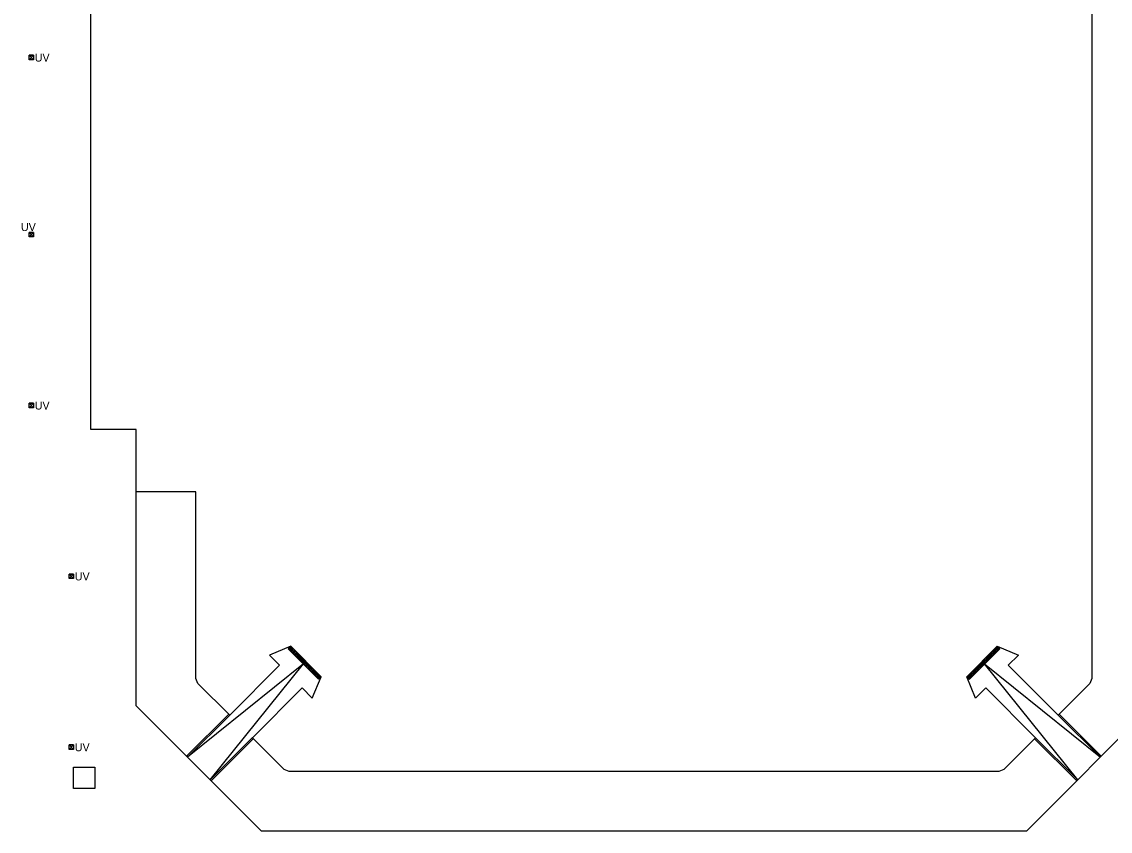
# Model space of a CAD drawing. Extents: x -264222 to -263676, y -1242344 to -1242060.
# Drawn here: x -263921.9 to -263799.5, y -1242241.5 to -1242150.5 of the extents above; entities that cross this region are included whole.
import ezdxf

# ---------------------------------------------------------------- set-up
doc = ezdxf.new("R2010")
doc.units = 0
doc.layers.add('PROJEKT_DRS_OBRUBNIKY_KOMUNIKACIE', color=7, linetype='Continuous')
doc.layers.add('PROJEKT_DRS_UV_STAVBY', color=7, linetype='Continuous')

msp = doc.modelspace()

# ---------------------------------------------------------------- linework, layer by layer
at = {"layer": 'PROJEKT_DRS_OBRUBNIKY_KOMUNIKACIE'}
for p, q in [((-263805.39, -1242228.4), (-263800.65, -1242233.14)), ((-263805.28, -1242228.3), (-263800.55, -1242233.04)), ((-263808.09, -1242231.02), (-263803.31, -1242235.8)), ((-263807.99, -1242230.91), (-263803.2, -1242235.69)), ((-263916.09, -1242234.26), (-263913.69, -1242234.26)), ((-263916.09, -1242236.66), (-263916.09, -1242234.26)), ((-263913.69, -1242234.26), (-263913.69, -1242236.66)), ((-263913.69, -1242236.66), (-263916.09, -1242236.66))]:
    msp.add_line(p, q, dxfattribs=at)
for points in [[(-263794.89, -1242227.38), (-263808.97, -1242241.46), (-263894.97, -1242241.46), (-263909.04, -1242227.38), (-263909.04, -1242196.33), (-263914.14, -1242196.33), (-263914.14, -1242132.43), (-263909.04, -1242132.43), (-263909.04, -1242101.38), (-263894.97, -1242087.31), (-263808.97, -1242087.31), (-263794.89, -1242101.38), (-263794.89, -1242227.38)], [(-263909.04, -1242125.43), (-263902.34, -1242125.43), (-263902.34, -1242104.48), (-263902.11, -1242103.93), (-263898.54, -1242100.36), (-263895.99, -1242097.81), (-263892.42, -1242094.24), (-263891.87, -1242094.01), (-263812.07, -1242094.01), (-263811.51, -1242094.24), (-263801.82, -1242103.93), (-263801.59, -1242104.48), (-263801.59, -1242224.28), (-263801.82, -1242224.84), (-263805.39, -1242228.41)], [(-263898.54, -1242228.41), (-263902.11, -1242224.84), (-263902.34, -1242224.28), (-263902.34, -1242203.33), (-263909.04, -1242203.33)], [(-263891.67, -1242220.67), (-263894.07, -1242221.67), (-263892.94, -1242222.81), (-263898.54, -1242228.41)], [(-263895.99, -1242230.96), (-263890.39, -1242225.35), (-263889.25, -1242226.49), (-263888.26, -1242224.09), (-263891.67, -1242220.67)], [(-263807.94, -1242230.96), (-263813.54, -1242225.35), (-263814.68, -1242226.49), (-263815.68, -1242224.09), (-263812.26, -1242220.67)], [(-263812.26, -1242220.67), (-263809.86, -1242221.67), (-263811, -1242222.81), (-263805.39, -1242228.41)], [(-263903.28, -1242233.15), (-263900.73, -1242235.69), (-263890.25, -1242222.66), (-263903.28, -1242233.15)], [(-263803.2, -1242235.69), (-263813.68, -1242222.66), (-263800.65, -1242233.14)], [(-263898.65, -1242228.3), (-263903.39, -1242233.03), (-263900.63, -1242235.8), (-263895.88, -1242231.05)], [(-263898.54, -1242228.41), (-263903.28, -1242233.14), (-263900.73, -1242235.69), (-263895.98, -1242230.94)], [(-263807.94, -1242230.96), (-263811.51, -1242234.53), (-263812.07, -1242234.76), (-263891.87, -1242234.76), (-263892.42, -1242234.53), (-263895.99, -1242230.96)]]:
    msp.add_lwpolyline(points, dxfattribs=at)
at = {"layer": 'PROJEKT_DRS_UV_STAVBY'}
for p, q in [((-263888.55, -1242224.36), (-263891.96, -1242220.95)), ((-263891.66, -1242220.97), (-263891.96, -1242220.95)), ((-263891.92, -1242221), (-263891.78, -1242220.86)), ((-263891.83, -1242221.08), (-263891.69, -1242220.94)), ((-263888.41, -1242224.23), (-263891.82, -1242220.81)), ((-263891.52, -1242220.83), (-263891.82, -1242220.81)), ((-263891.82, -1242220.82), (-263891.8, -1242221.11)), ((-263891.77, -1242220.85), (-263891.63, -1242220.71)), ((-263891.74, -1242221.17), (-263891.6, -1242221.03)), ((-263891.68, -1242220.94), (-263891.54, -1242220.8)), ((-263891.67, -1242220.68), (-263891.66, -1242220.97)), ((-263891.65, -1242221.26), (-263891.51, -1242221.12)), ((-263891.59, -1242221.03), (-263891.45, -1242220.89)), ((-263891.56, -1242221.35), (-263891.42, -1242221.21)), ((-263891.5, -1242221.12), (-263891.36, -1242220.98)), ((-263891.48, -1242221.44), (-263891.34, -1242221.3)), ((-263891.42, -1242221.21), (-263891.27, -1242221.07)), ((-263891.39, -1242221.53), (-263891.25, -1242221.39)), ((-263891.33, -1242221.3), (-263891.19, -1242221.16)), ((-263891.3, -1242221.61), (-263891.16, -1242221.47)), ((-263891.24, -1242221.38), (-263891.1, -1242221.24)), ((-263891.15, -1242221.47), (-263891.01, -1242221.33)), ((-263891.06, -1242221.56), (-263890.92, -1242221.42)), ((-263815.53, -1242224.23), (-263812.12, -1242220.81)), ((-263815.38, -1242224.36), (-263811.97, -1242220.95)), ((-263812.9, -1242221.6), (-263813.04, -1242221.45)), ((-263812.81, -1242221.51), (-263812.95, -1242221.36)), ((-263812.72, -1242221.42), (-263812.86, -1242221.28)), ((-263812.64, -1242221.33), (-263812.78, -1242221.19)), ((-263812.58, -1242221.56), (-263812.72, -1242221.41)), ((-263812.55, -1242221.24), (-263812.69, -1242221.1)), ((-263812.49, -1242221.47), (-263812.63, -1242221.33)), ((-263812.46, -1242221.16), (-263812.6, -1242221.01)), ((-263812.4, -1242221.38), (-263812.54, -1242221.24)), ((-263812.37, -1242221.07), (-263812.51, -1242220.92)), ((-263812.31, -1242221.29), (-263812.45, -1242221.15)), ((-263812.42, -1242220.83), (-263812.12, -1242220.81)), ((-263812.28, -1242220.98), (-263812.42, -1242220.83)), ((-263812.23, -1242221.2), (-263812.36, -1242221.06)), ((-263812.19, -1242220.89), (-263812.33, -1242220.75)), ((-263812.26, -1242220.68), (-263812.28, -1242220.97)), ((-263812.28, -1242220.97), (-263811.98, -1242220.95)), ((-263812.14, -1242221.12), (-263812.28, -1242220.97)), ((-263812.05, -1242221.03), (-263812.19, -1242220.88)), ((-263812.12, -1242220.82), (-263812.14, -1242221.11)), ((-263891.21, -1242221.7), (-263891.07, -1242221.56)), ((-263891.12, -1242221.79), (-263890.98, -1242221.65)), ((-263891.03, -1242221.88), (-263890.89, -1242221.74)), ((-263890.97, -1242221.65), (-263890.83, -1242221.51)), ((-263890.95, -1242221.97), (-263890.81, -1242221.83)), ((-263890.89, -1242221.74), (-263890.74, -1242221.6)), ((-263890.86, -1242222.06), (-263890.72, -1242221.92)), ((-263890.8, -1242221.83), (-263890.66, -1242221.69)), ((-263890.77, -1242222.15), (-263890.63, -1242222)), ((-263890.71, -1242221.91), (-263890.57, -1242221.77)), ((-263890.68, -1242222.23), (-263890.54, -1242222.09)), ((-263890.62, -1242222), (-263890.48, -1242221.86)), ((-263890.59, -1242222.32), (-263890.45, -1242222.18)), ((-263890.53, -1242222.09), (-263890.39, -1242221.95)), ((-263890.5, -1242222.41), (-263890.36, -1242222.27)), ((-263890.44, -1242222.18), (-263890.3, -1242222.04)), ((-263890.42, -1242222.5), (-263890.27, -1242222.36)), ((-263890.35, -1242222.27), (-263890.21, -1242222.13)), ((-263890.33, -1242222.59), (-263890.19, -1242222.45)), ((-263890.27, -1242222.36), (-263890.13, -1242222.22)), ((-263890.24, -1242222.68), (-263890.1, -1242222.53)), ((-263890.18, -1242222.45), (-263890.04, -1242222.3)), ((-263890.15, -1242222.76), (-263890.01, -1242222.62)), ((-263890.09, -1242222.53), (-263889.95, -1242222.39)), ((-263890, -1242222.62), (-263889.86, -1242222.48)), ((-263889.91, -1242222.71), (-263889.77, -1242222.57)), ((-263889.82, -1242222.8), (-263889.68, -1242222.66)), ((-263814.14, -1242222.84), (-263814.28, -1242222.69)), ((-263814.05, -1242222.75), (-263814.19, -1242222.6)), ((-263813.96, -1242222.66), (-263814.1, -1242222.51)), ((-263813.87, -1242222.57), (-263814.01, -1242222.43)), ((-263813.82, -1242222.8), (-263813.96, -1242222.65)), ((-263813.78, -1242222.48), (-263813.92, -1242222.34)), ((-263813.73, -1242222.71), (-263813.87, -1242222.56)), ((-263813.7, -1242222.39), (-263813.84, -1242222.25)), ((-263813.64, -1242222.62), (-263813.78, -1242222.48)), ((-263813.61, -1242222.3), (-263813.75, -1242222.16)), ((-263813.55, -1242222.53), (-263813.69, -1242222.39)), ((-263813.52, -1242222.22), (-263813.66, -1242222.07)), ((-263813.46, -1242222.44), (-263813.6, -1242222.3)), ((-263813.43, -1242222.13), (-263813.57, -1242221.98)), ((-263813.37, -1242222.35), (-263813.51, -1242222.21)), ((-263813.34, -1242222.04), (-263813.48, -1242221.89)), ((-263813.29, -1242222.27), (-263813.42, -1242222.12)), ((-263813.25, -1242221.95), (-263813.39, -1242221.81)), ((-263813.2, -1242222.18), (-263813.34, -1242222.03)), ((-263813.17, -1242221.86), (-263813.31, -1242221.72)), ((-263813.11, -1242222.09), (-263813.25, -1242221.94)), ((-263813.08, -1242221.77), (-263813.22, -1242221.63)), ((-263813.02, -1242222), (-263813.16, -1242221.86)), ((-263812.99, -1242221.69), (-263813.13, -1242221.54)), ((-263812.93, -1242221.91), (-263813.07, -1242221.77)), ((-263812.84, -1242221.82), (-263812.98, -1242221.68)), ((-263812.76, -1242221.73), (-263812.89, -1242221.59)), ((-263812.67, -1242221.65), (-263812.81, -1242221.5)), ((-263890.06, -1242222.85), (-263889.92, -1242222.71)), ((-263889.97, -1242222.94), (-263889.83, -1242222.8)), ((-263889.89, -1242223.03), (-263889.74, -1242222.89)), ((-263889.8, -1242223.12), (-263889.66, -1242222.98)), ((-263889.74, -1242222.89), (-263889.6, -1242222.75)), ((-263889.71, -1242223.21), (-263889.57, -1242223.06)), ((-263889.65, -1242222.98), (-263889.51, -1242222.83)), ((-263889.62, -1242223.29), (-263889.48, -1242223.15)), ((-263889.56, -1242223.06), (-263889.42, -1242222.92)), ((-263889.53, -1242223.38), (-263889.39, -1242223.24)), ((-263889.47, -1242223.15), (-263889.33, -1242223.01)), ((-263889.44, -1242223.47), (-263889.3, -1242223.33)), ((-263889.38, -1242223.24), (-263889.24, -1242223.1)), ((-263889.36, -1242223.56), (-263889.21, -1242223.42)), ((-263889.29, -1242223.33), (-263889.15, -1242223.19)), ((-263889.27, -1242223.65), (-263889.13, -1242223.51)), ((-263889.21, -1242223.42), (-263889.06, -1242223.28)), ((-263889.18, -1242223.74), (-263889.04, -1242223.6)), ((-263889.12, -1242223.51), (-263888.98, -1242223.36)), ((-263889.09, -1242223.82), (-263888.95, -1242223.68)), ((-263889.03, -1242223.59), (-263888.89, -1242223.45)), ((-263889, -1242223.91), (-263888.86, -1242223.77)), ((-263888.94, -1242223.68), (-263888.8, -1242223.54)), ((-263888.91, -1242224), (-263888.77, -1242223.86)), ((-263888.85, -1242223.77), (-263888.71, -1242223.63)), ((-263888.76, -1242223.86), (-263888.62, -1242223.72)), ((-263888.68, -1242223.95), (-263888.53, -1242223.81)), ((-263888.59, -1242224.04), (-263888.45, -1242223.9)), ((-263815.38, -1242224.07), (-263815.52, -1242223.93)), ((-263815.29, -1242223.98), (-263815.43, -1242223.84)), ((-263815.2, -1242223.9), (-263815.34, -1242223.75)), ((-263815.11, -1242223.81), (-263815.25, -1242223.66)), ((-263815.05, -1242224.03), (-263815.19, -1242223.89)), ((-263815.02, -1242223.72), (-263815.16, -1242223.57)), ((-263814.97, -1242223.94), (-263815.1, -1242223.8)), ((-263814.93, -1242223.63), (-263815.07, -1242223.49)), ((-263814.88, -1242223.86), (-263815.02, -1242223.71)), ((-263814.85, -1242223.54), (-263814.99, -1242223.4)), ((-263814.79, -1242223.77), (-263814.93, -1242223.62)), ((-263814.76, -1242223.45), (-263814.9, -1242223.31)), ((-263814.7, -1242223.68), (-263814.84, -1242223.54)), ((-263814.67, -1242223.37), (-263814.81, -1242223.22)), ((-263814.61, -1242223.59), (-263814.75, -1242223.45)), ((-263814.58, -1242223.28), (-263814.72, -1242223.13)), ((-263814.52, -1242223.5), (-263814.66, -1242223.36)), ((-263814.49, -1242223.19), (-263814.63, -1242223.04)), ((-263814.44, -1242223.41), (-263814.57, -1242223.27)), ((-263814.4, -1242223.1), (-263814.54, -1242222.96)), ((-263814.35, -1242223.33), (-263814.49, -1242223.18)), ((-263814.32, -1242223.01), (-263814.45, -1242222.87)), ((-263814.26, -1242223.24), (-263814.4, -1242223.09)), ((-263814.23, -1242222.92), (-263814.37, -1242222.78)), ((-263814.17, -1242223.15), (-263814.31, -1242223.01)), ((-263814.08, -1242223.06), (-263814.22, -1242222.92)), ((-263813.99, -1242222.97), (-263814.13, -1242222.83)), ((-263813.9, -1242222.88), (-263814.04, -1242222.74)), ((-263888.82, -1242224.09), (-263888.68, -1242223.95)), ((-263888.74, -1242224.18), (-263888.6, -1242224.04)), ((-263888.65, -1242224.27), (-263888.51, -1242224.13)), ((-263888.56, -1242224.35), (-263888.42, -1242224.21)), ((-263888.26, -1242224.09), (-263888.55, -1242224.36)), ((-263888.5, -1242224.12), (-263888.36, -1242223.98)), ((-263888.41, -1242224.21), (-263888.27, -1242224.07)), ((-263815.68, -1242224.09), (-263815.38, -1242224.36)), ((-263815.46, -1242224.16), (-263815.6, -1242224.02)), ((-263815.32, -1242224.3), (-263815.46, -1242224.15)), ((-263815.23, -1242224.21), (-263815.37, -1242224.07)), ((-263815.14, -1242224.12), (-263815.28, -1242223.98))]:
    msp.add_line(p, q, dxfattribs=at)
for points in [[(-263921.09, -1242154.76), (-263921.09, -1242154.26), (-263920.59, -1242154.26), (-263920.59, -1242154.76), (-263921.09, -1242154.76), (-263920.59, -1242154.26), (-263921.09, -1242154.26), (-263920.59, -1242154.76)], [(-263921.09, -1242174.66), (-263921.09, -1242174.16), (-263920.59, -1242174.16), (-263920.59, -1242174.66), (-263921.09, -1242174.66), (-263920.59, -1242174.16), (-263921.09, -1242174.16), (-263920.59, -1242174.66)], [(-263921.09, -1242193.86), (-263921.09, -1242193.36), (-263920.59, -1242193.36), (-263920.59, -1242193.86), (-263921.09, -1242193.86), (-263920.59, -1242193.36), (-263921.09, -1242193.36), (-263920.59, -1242193.86)], [(-263916.59, -1242213.06), (-263916.59, -1242212.56), (-263916.09, -1242212.56), (-263916.09, -1242213.06), (-263916.59, -1242213.06), (-263916.09, -1242212.56), (-263916.59, -1242212.56), (-263916.09, -1242213.06)], [(-263888.41, -1242224.23), (-263891.82, -1242220.81), (-263891.96, -1242220.95)], [(-263891.82, -1242220.82), (-263891.96, -1242220.95), (-263891.8, -1242221.11), (-263891.66, -1242220.97), (-263891.82, -1242220.81)], [(-263888.26, -1242224.09), (-263891.67, -1242220.68), (-263891.82, -1242220.81)], [(-263891.67, -1242220.68), (-263891.82, -1242220.81), (-263891.66, -1242220.97), (-263891.52, -1242220.83), (-263891.67, -1242220.68)], [(-263815.68, -1242224.09), (-263812.26, -1242220.68), (-263812.12, -1242220.81)], [(-263815.53, -1242224.23), (-263812.12, -1242220.81), (-263811.97, -1242220.95)], [(-263812.26, -1242220.68), (-263812.12, -1242220.81), (-263812.28, -1242220.97), (-263812.42, -1242220.83), (-263812.26, -1242220.68)], [(-263812.12, -1242220.82), (-263811.97, -1242220.95), (-263812.14, -1242221.11), (-263812.28, -1242220.97), (-263812.12, -1242220.81)], [(-263916.59, -1242232.26), (-263916.59, -1242231.76), (-263916.09, -1242231.76), (-263916.09, -1242232.26), (-263916.59, -1242232.26), (-263916.09, -1242231.76), (-263916.59, -1242231.76), (-263916.09, -1242232.26)]]:
    msp.add_lwpolyline(points, dxfattribs=at)

# ---------------------------------------------------------------- texts
for p in [(-263920.46, -1242154.97), (-263922.01, -1242174.01), (-263920.46, -1242194.07), (-263915.96, -1242213.27), (-263915.96, -1242232.47)]:
    msp.add_text('UV', height=0.9, rotation=359.8587, dxfattribs=at).set_placement(p)

doc.saveas('drawing.dxf')
